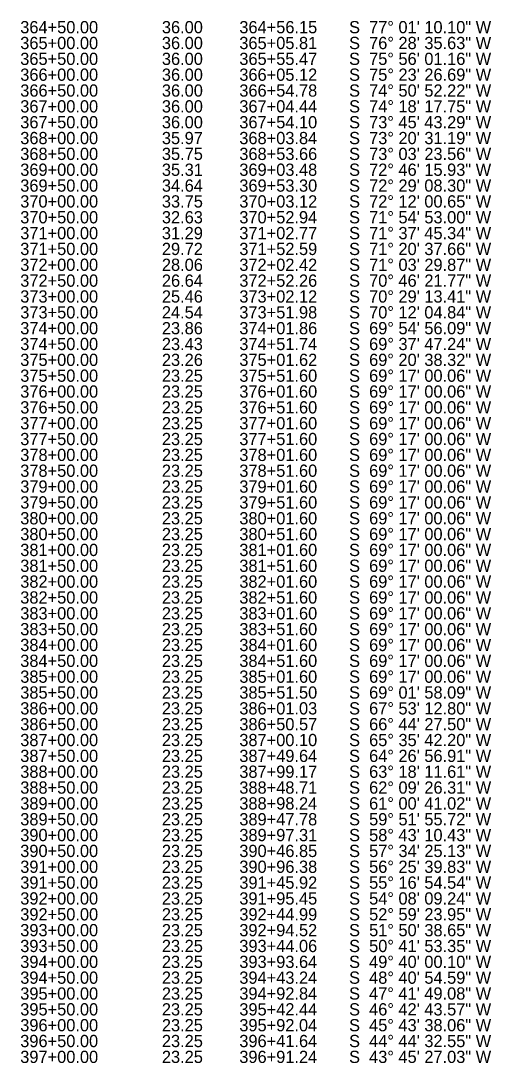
# Model space of a CAD drawing. Extents: x 1602163 to 1612907, y 1087635 to 1096265.
# Drawn here: x 1602178 to 1602409, y 1095110 to 1095621 of the extents above; entities that cross this region are included whole.
import ezdxf

# ---------------------------------------------------------------- set-up
doc = ezdxf.new("R2010")
doc.units = 0
doc.layers.add('RD_SHT_TX', color=7, linetype='Continuous')

msp = doc.modelspace()

# ---------------------------------------------------------------- texts
at = {"layer": 'RD_SHT_TX'}
for s, p in [('       364+50.00              36.00        364+56.15       S  77° 01\' 10.10" W  ', (1602162.4, 1095614.69)), ('       365+00.00              36.00        365+05.81       S  76° 28\' 35.63" W  ', (1602162.4, 1095606.93)), ('       365+50.00              36.00        365+55.47       S  75° 56\' 01.16" W  ', (1602162.4, 1095599.16)), ('       366+00.00              36.00        366+05.12       S  75° 23\' 26.69" W  ', (1602162.4, 1095591.4)), ('       366+50.00              36.00        366+54.78       S  74° 50\' 52.22" W  ', (1602162.4, 1095583.63)), ('       367+00.00              36.00        367+04.44       S  74° 18\' 17.75" W  ', (1602162.4, 1095575.87)), ('       367+50.00              36.00        367+54.10       S  73° 45\' 43.29" W  ', (1602162.4, 1095568.1)), ('       368+00.00              35.97        368+03.84       S  73° 20\' 31.19" W  ', (1602162.4, 1095560.34)), ('       368+50.00              35.75        368+53.66       S  73° 03\' 23.56" W  ', (1602162.4, 1095552.57)), ('       369+00.00              35.31        369+03.48       S  72° 46\' 15.93" W  ', (1602162.4, 1095544.81)), ('       369+50.00              34.64        369+53.30       S  72° 29\' 08.30" W  ', (1602162.4, 1095537.04)), ('       370+00.00              33.75        370+03.12       S  72° 12\' 00.65" W  ', (1602162.4, 1095529.28)), ('       370+50.00              32.63        370+52.94       S  71° 54\' 53.00" W  ', (1602162.4, 1095521.51)), ('       371+00.00              31.29        371+02.77       S  71° 37\' 45.34" W  ', (1602162.4, 1095513.75)), ('       371+50.00              29.72        371+52.59       S  71° 20\' 37.66" W  ', (1602162.4, 1095505.98)), ('       372+00.00              28.06        372+02.42       S  71° 03\' 29.87" W  ', (1602162.4, 1095498.22)), ('       372+50.00              26.64        372+52.26       S  70° 46\' 21.77" W  ', (1602162.4, 1095490.45)), ('       373+00.00              25.46        373+02.12       S  70° 29\' 13.41" W  ', (1602162.4, 1095482.68)), ('       373+50.00              24.54        373+51.98       S  70° 12\' 04.84" W  ', (1602162.4, 1095474.92)), ('       374+00.00              23.86        374+01.86       S  69° 54\' 56.09" W  ', (1602162.4, 1095467.15)), ('       374+50.00              23.43        374+51.74       S  69° 37\' 47.24" W  ', (1602162.4, 1095459.39)), ('       375+00.00              23.26        375+01.62       S  69° 20\' 38.32" W  ', (1602162.4, 1095451.62)), ('       375+50.00              23.25        375+51.60       S  69° 17\' 00.06" W  ', (1602162.4, 1095443.86)), ('       376+00.00              23.25        376+01.60       S  69° 17\' 00.06" W  ', (1602162.4, 1095436.09)), ('       376+50.00              23.25        376+51.60       S  69° 17\' 00.06" W  ', (1602162.4, 1095428.33)), ('       377+00.00              23.25        377+01.60       S  69° 17\' 00.06" W  ', (1602162.4, 1095420.56)), ('       377+50.00              23.25        377+51.60       S  69° 17\' 00.06" W  ', (1602162.4, 1095412.8)), ('       378+00.00              23.25        378+01.60       S  69° 17\' 00.06" W  ', (1602162.4, 1095405.03)), ('       378+50.00              23.25        378+51.60       S  69° 17\' 00.06" W  ', (1602162.4, 1095397.27)), ('       379+00.00              23.25        379+01.60       S  69° 17\' 00.06" W  ', (1602162.4, 1095389.5)), ('       379+50.00              23.25        379+51.60       S  69° 17\' 00.06" W  ', (1602162.4, 1095381.74)), ('       380+00.00              23.25        380+01.60       S  69° 17\' 00.06" W  ', (1602162.4, 1095373.97)), ('       380+50.00              23.25        380+51.60       S  69° 17\' 00.06" W  ', (1602162.4, 1095366.21)), ('       381+00.00              23.25        381+01.60       S  69° 17\' 00.06" W  ', (1602162.4, 1095358.44)), ('       381+50.00              23.25        381+51.60       S  69° 17\' 00.06" W  ', (1602162.4, 1095350.68)), ('       382+00.00              23.25        382+01.60       S  69° 17\' 00.06" W  ', (1602162.4, 1095342.91)), ('       382+50.00              23.25        382+51.60       S  69° 17\' 00.06" W  ', (1602162.4, 1095335.14)), ('       383+00.00              23.25        383+01.60       S  69° 17\' 00.06" W  ', (1602162.4, 1095327.38)), ('       383+50.00              23.25        383+51.60       S  69° 17\' 00.06" W  ', (1602162.4, 1095319.61)), ('       384+00.00              23.25        384+01.60       S  69° 17\' 00.06" W  ', (1602162.4, 1095311.85)), ('       384+50.00              23.25        384+51.60       S  69° 17\' 00.06" W  ', (1602162.4, 1095304.08)), ('       385+00.00              23.25        385+01.60       S  69° 17\' 00.06" W  ', (1602162.4, 1095296.32)), ('       385+50.00              23.25        385+51.50       S  69° 01\' 58.09" W  ', (1602162.4, 1095288.55)), ('       386+00.00              23.25        386+01.03       S  67° 53\' 12.80" W  ', (1602162.4, 1095280.79)), ('       386+50.00              23.25        386+50.57       S  66° 44\' 27.50" W  ', (1602162.4, 1095273.02)), ('       387+00.00              23.25        387+00.10       S  65° 35\' 42.20" W  ', (1602162.4, 1095265.26)), ('       387+50.00              23.25        387+49.64       S  64° 26\' 56.91" W  ', (1602162.4, 1095257.49)), ('       388+00.00              23.25        387+99.17       S  63° 18\' 11.61" W  ', (1602162.4, 1095249.73)), ('       388+50.00              23.25        388+48.71       S  62° 09\' 26.31" W  ', (1602162.4, 1095241.96)), ('       389+00.00              23.25        388+98.24       S  61° 00\' 41.02" W  ', (1602162.4, 1095234.2)), ('       389+50.00              23.25        389+47.78       S  59° 51\' 55.72" W  ', (1602162.4, 1095226.43)), ('       390+00.00              23.25        389+97.31       S  58° 43\' 10.43" W  ', (1602162.4, 1095218.67)), ('       390+50.00              23.25        390+46.85       S  57° 34\' 25.13" W  ', (1602162.4, 1095210.9)), ('       391+00.00              23.25        390+96.38       S  56° 25\' 39.83" W  ', (1602162.4, 1095203.14)), ('       391+50.00              23.25        391+45.92       S  55° 16\' 54.54" W  ', (1602162.4, 1095195.37)), ('       392+00.00              23.25        391+95.45       S  54° 08\' 09.24" W  ', (1602162.4, 1095187.61)), ('       392+50.00              23.25        392+44.99       S  52° 59\' 23.95" W  ', (1602162.4, 1095179.84)), ('       393+00.00              23.25        392+94.52       S  51° 50\' 38.65" W  ', (1602162.4, 1095172.07)), ('       393+50.00              23.25        393+44.06       S  50° 41\' 53.35" W  ', (1602162.4, 1095164.31)), ('       394+00.00              23.25        393+93.64       S  49° 40\' 00.10" W  ', (1602162.4, 1095156.54)), ('       394+50.00              23.25        394+43.24       S  48° 40\' 54.59" W  ', (1602162.4, 1095148.78)), ('       395+00.00              23.25        394+92.84       S  47° 41\' 49.08" W  ', (1602162.4, 1095141.01)), ('       395+50.00              23.25        395+42.44       S  46° 42\' 43.57" W  ', (1602162.4, 1095133.25)), ('       396+00.00              23.25        395+92.04       S  45° 43\' 38.06" W  ', (1602162.4, 1095125.48)), ('       396+50.00              23.25        396+41.64       S  44° 44\' 32.55" W  ', (1602162.4, 1095117.72)), ('       397+00.00              23.25        396+91.24       S  43° 45\' 27.03" W  ', (1602162.4, 1095109.95))]:
    msp.add_text(s, height=6, dxfattribs=at).set_placement(p)

doc.saveas('drawing.dxf')
